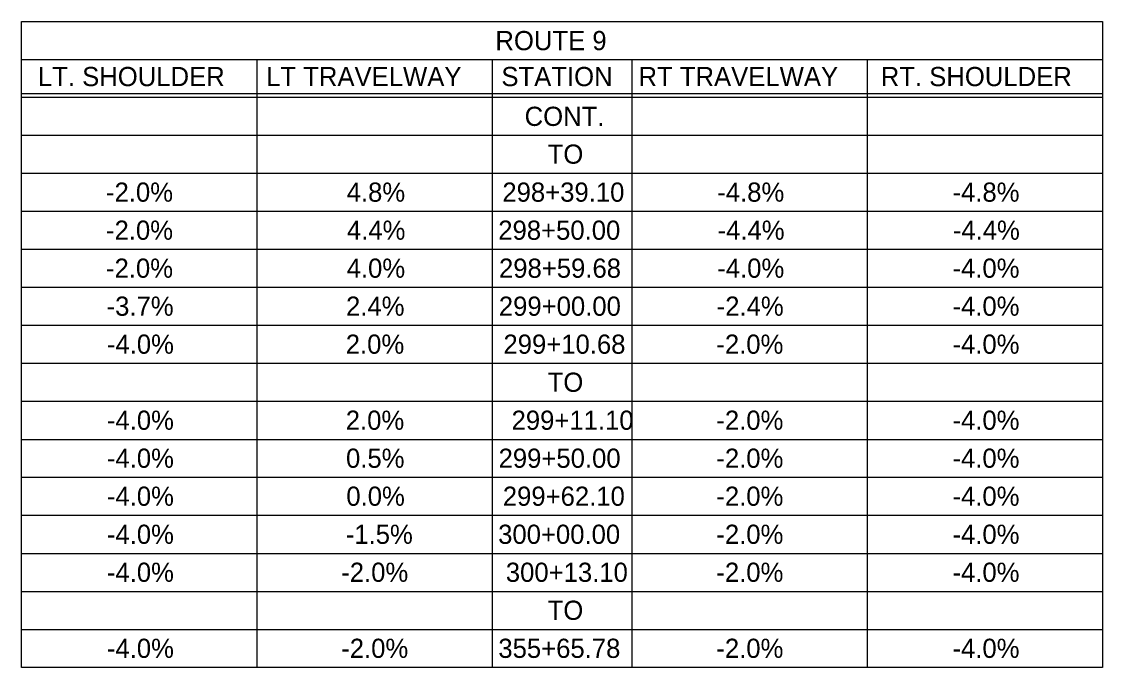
# Model space of a CAD drawing. Extents: x -15319374 to 1762012, y 465773 to 3693661.
# Drawn here: x -15316089.5 to -15315920.5, y 3691742.1 to 3691843.1 of the extents above; entities that cross this region are included whole.
import ezdxf

# ---------------------------------------------------------------- set-up
doc = ezdxf.new("R2010")
doc.units = 0
doc.layers.add('BORDER', color=7, linetype='Continuous')
doc.layers.add('DIMENSIONS', color=7, linetype='Continuous')

msp = doc.modelspace()

# ---------------------------------------------------------------- linework, layer by layer
at = {"layer": 'BORDER'}
for p, q in [((-15316052.68, 3691837.11), (-15316052.68, 3691742.1)), ((-15316015.92, 3691837.11), (-15316015.92, 3691742.1)), ((-15315994.04, 3691837.11), (-15315994.04, 3691742.1)), ((-15315957.27, 3691837.11), (-15315957.27, 3691742.1)), ((-15316089.45, 3691831.83), (-15315920.5, 3691831.83)), ((-15316089.45, 3691831.24), (-15315920.5, 3691831.24)), ((-15316089.45, 3691825.29), (-15315920.5, 3691825.29)), ((-15316089.45, 3691825.29), (-15315920.5, 3691825.29)), ((-15316089.45, 3691825.29), (-15315920.5, 3691825.29)), ((-15316089.45, 3691819.35), (-15315920.5, 3691819.35)), ((-15316089.45, 3691813.41), (-15315920.5, 3691813.41)), ((-15316089.45, 3691807.47), (-15315920.5, 3691807.47)), ((-15316089.45, 3691801.52), (-15315920.5, 3691801.52)), ((-15316089.45, 3691795.58), (-15315920.5, 3691795.58)), ((-15316089.45, 3691789.64), (-15315920.5, 3691789.64)), ((-15316089.45, 3691783.7), (-15315920.5, 3691783.7)), ((-15316089.45, 3691777.75), (-15315920.5, 3691777.75)), ((-15316089.45, 3691771.81), (-15315920.5, 3691771.81)), ((-15316089.45, 3691765.87), (-15315920.5, 3691765.87)), ((-15316089.45, 3691759.92), (-15315920.5, 3691759.92)), ((-15316089.45, 3691753.98), (-15315920.5, 3691753.98)), ((-15316089.45, 3691748.04), (-15315920.5, 3691748.04))]:
    msp.add_line(p, q, dxfattribs=at)
msp.add_lwpolyline([(-15316089.45, 3691837.11), (-15316089.45, 3691843.06), (-15315920.5, 3691843.06), (-15315920.5, 3691837.11)], dxfattribs=at)
msp.add_lwpolyline([(-15316089.45, 3691837.11), (-15315920.5, 3691837.11), (-15315920.5, 3691742.1), (-15316089.45, 3691742.1)], close=True, dxfattribs=at)

# ---------------------------------------------------------------- texts
at = {"layer": 'DIMENSIONS'}
for s, p in [('ROUTE 9', (-15316015.39, 3691838.59)), ('LT. SHOULDER', (-15316086.9, 3691832.97)), ('LT TRAVELWAY', (-15316051.23, 3691832.97)), ('STATION', (-15316014.45, 3691832.97)), ('RT TRAVELWAY', (-15315993.02, 3691832.97)), ('RT. SHOULDER', (-15315955.15, 3691832.97)), ('CONT.', (-15316010.82, 3691826.75)), ('TO', (-15316007.22, 3691820.84)), ('-2.0%', (-15316076.26, 3691814.9)), ('4.8%', (-15316038.64, 3691814.9)), ('298+39.10', (-15316014.3, 3691814.9)), ('-4.8%', (-15315980.71, 3691814.9)), ('-4.8%', (-15315943.94, 3691814.9)), ('-2.0%', (-15316076.26, 3691808.95)), ('4.4%', (-15316038.6, 3691808.95)), ('298+50.00', (-15316014.94, 3691808.95)), ('-4.4%', (-15315980.66, 3691808.95)), ('-4.4%', (-15315943.89, 3691808.95)), ('-2.0%', (-15316076.26, 3691803.01)), ('4.0%', (-15316038.64, 3691803.01)), ('298+59.68', (-15316014.83, 3691803.01)), ('-4.0%', (-15315980.71, 3691803.01)), ('-4.0%', (-15315943.94, 3691803.01)), ('-3.7%', (-15316076.17, 3691797.07)), ('2.4%', (-15316038.74, 3691797.07)), ('299+00.00', (-15316014.85, 3691797.07)), ('-2.4%', (-15315980.8, 3691797.07)), ('-4.0%', (-15315943.94, 3691797.07)), ('-4.0%', (-15316076.12, 3691791.13)), ('2.0%', (-15316038.78, 3691791.13)), ('299+10.68', (-15316014.13, 3691791.13)), ('-2.0%', (-15315980.85, 3691791.13)), ('-4.0%', (-15315943.94, 3691791.13)), ('TO', (-15316007.22, 3691785.18)), ('-4.0%', (-15316076.12, 3691779.24)), ('2.0%', (-15316038.78, 3691779.24)), ('299+11.10', (-15316012.86, 3691779.24)), ('-2.0%', (-15315980.85, 3691779.24)), ('-4.0%', (-15315943.94, 3691779.24)), ('-4.0%', (-15316076.12, 3691773.3)), ('0.5%', (-15316038.74, 3691773.3)), ('299+50.00', (-15316014.89, 3691773.3)), ('-2.0%', (-15315980.85, 3691773.3)), ('-4.0%', (-15315943.94, 3691773.3)), ('-4.0%', (-15316076.12, 3691767.36)), ('0.0%', (-15316038.69, 3691767.36)), ('299+62.10', (-15316014.23, 3691767.36)), ('-2.0%', (-15315980.85, 3691767.36)), ('-4.0%', (-15315943.94, 3691767.36)), ('-4.0%', (-15316076.12, 3691761.41)), ('-1.5%', (-15316038.78, 3691761.41)), ('300+00.00', (-15316014.96, 3691761.41)), ('-2.0%', (-15315980.85, 3691761.41)), ('-4.0%', (-15315943.94, 3691761.41)), ('-4.0%', (-15316076.12, 3691755.47)), ('-2.0%', (-15316039.49, 3691755.47)), ('300+13.10', (-15316013.76, 3691755.47)), ('-2.0%', (-15315980.85, 3691755.47)), ('-4.0%', (-15315943.94, 3691755.47)), ('TO', (-15316007.22, 3691749.53)), ('-4.0%', (-15316076.12, 3691743.58)), ('-2.0%', (-15316039.49, 3691743.58)), ('355+65.78', (-15316014.93, 3691743.58)), ('-2.0%', (-15315980.85, 3691743.58)), ('-4.0%', (-15315943.94, 3691743.58))]:
    msp.add_text(s, height=3, dxfattribs=at).set_placement(p)

doc.saveas('drawing.dxf')
